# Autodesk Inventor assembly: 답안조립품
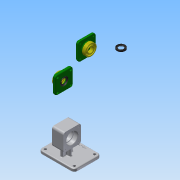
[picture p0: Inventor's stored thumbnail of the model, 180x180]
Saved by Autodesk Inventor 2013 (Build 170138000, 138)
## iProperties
Created: 2020-11
Part Number: 답안조립품
Document SubType Name: Assembly
Designer: Administrator
Author: Administrator
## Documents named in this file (5)
- C:\Users\Administrator\Desktop\701106v1047\답안조립품.iam
- C:\Users\Administrator\Desktop\701106v1047\본체.ipt
- C:\Users\Administrator\Desktop\701106v1047\베어링 6004.ipt
- C:\Users\Administrator\Desktop\701106v1047\오일 실 17 30 5.ipt
- C:\Users\Administrator\Desktop\701106v1047\커버.ipt
